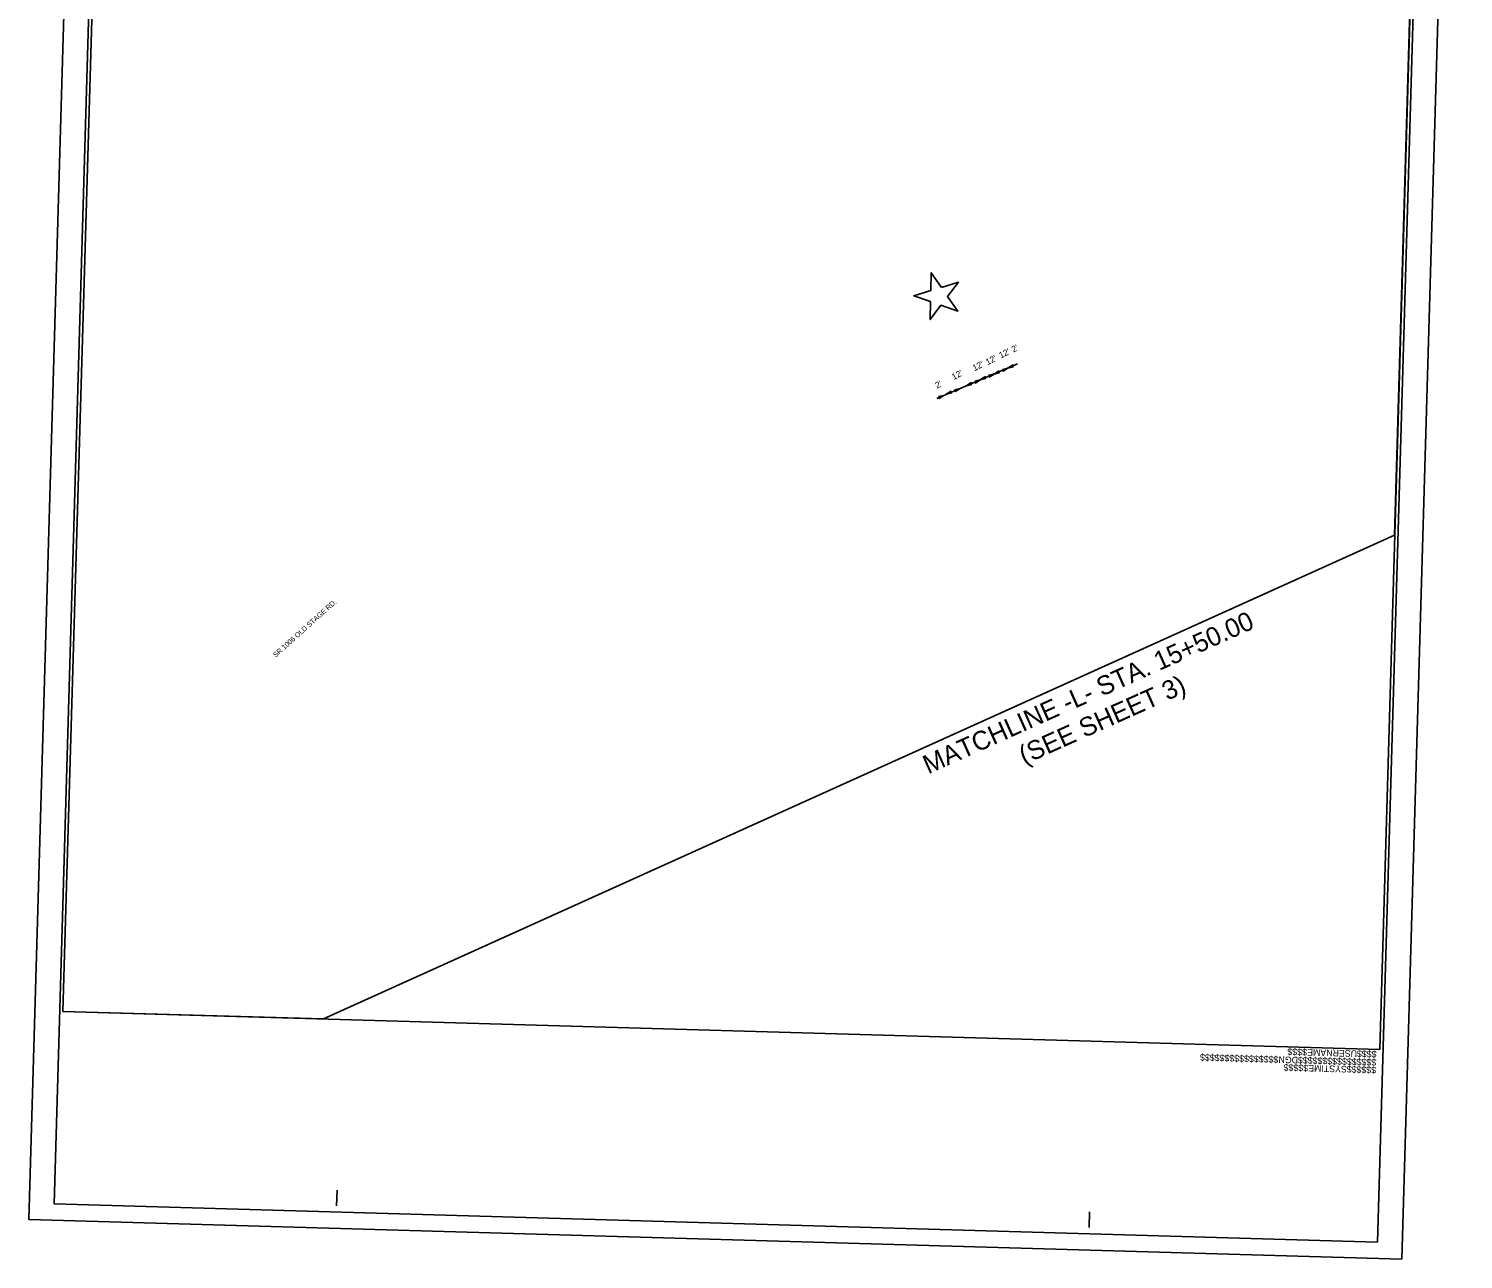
# Model space of a CAD drawing. Extents: x 2097002 to 2098146, y 685127 to 687089.
# Drawn here: x 2097002 to 2098146, y 685127 to 686108 of the extents above; entities that cross this region are included whole.
import ezdxf

# ---------------------------------------------------------------- set-up
doc = ezdxf.new("R2010")
doc.units = 0
for name, color, linetype in [('Default', 7, 'Continuous'), ('Matchline', 7, 'Continuous'), ('Matchline Text', 7, 'Continuous'), ('Sheet Layout Plan Border', 7, 'Continuous'), ('Sheet Plan CELL', 7, 'Continuous'), ('Sheet Plot Border Inside CELL', 7, 'Continuous'), ('Sheet Plot Border Outside CELL', 7, 'Continuous'), ('Text', 7, 'Continuous')]:
    doc.layers.add(name, color=color, linetype=linetype)

msp = doc.modelspace()

# ---------------------------------------------------------------- linework, layer by layer
at = {"layer": 'Default'}
msp.add_line((2097790.3, 685840.9), (2097725.9, 685813.5), dxfattribs=at)
msp.add_lwpolyline([(2097729.5, 685901.9), (2097721.4, 685913.6), (2097721.1, 685899.4), (2097707.5, 685895.2), (2097720.9, 685890.6), (2097720.7, 685876.3), (2097729.2, 685887.7), (2097742.7, 685883), (2097734.5, 685894.7), (2097743.1, 685906.1), (2097729.5, 685901.9)], dxfattribs=at)
for points in [[(2097776, 685834), (2097771.6, 685832.9), (2097775.4, 685835.4), (2097775.2, 685834.5)], [(2097778.2, 685836.6), (2097782.6, 685837.6), (2097778.8, 685835.1), (2097779, 685836.1)], [(2097787.1, 685838.7), (2097782.6, 685837.6), (2097786.5, 685840.1), (2097786.3, 685839.2)], [(2097753.9, 685824.6), (2097749.5, 685823.6), (2097753.3, 685826.1), (2097753.1, 685825.1)], [(2097756.1, 685827.2), (2097760.5, 685828.2), (2097756.7, 685825.7), (2097756.9, 685826.7)], [(2097765, 685829.3), (2097760.5, 685828.2), (2097764.4, 685830.8), (2097764.2, 685829.8)], [(2097767.1, 685831.9), (2097771.6, 685832.9), (2097767.7, 685830.4), (2097767.9, 685831.4)], [(2097727.1, 685814.9), (2097731.5, 685815.9), (2097727.7, 685813.4), (2097727.9, 685814.4)], [(2097737.9, 685817.8), (2097733.4, 685816.7), (2097737.3, 685819.2), (2097737.1, 685818.3)], [(2097740, 685820.4), (2097744.4, 685821.4), (2097740.6, 685818.9), (2097740.8, 685819.9)]]:
    msp.add_lwpolyline(points, close=True, dxfattribs=at)
at = {"layer": 'Matchline'}
msp.add_line((2097694.7, 685525.6), (2098013.7, 685669.6), dxfattribs=at)
at = {"layer": 'Sheet Layout Plan Border'}
msp.add_lwpolyline([(2098110.7, 686386.5), (2098090.8, 685704.4), (2097236.9, 685319), (2097029.4, 685325), (2097061.3, 686424.4), (2097062.8, 686473.8), (2097066.9, 686614.9), (2097306.9, 686607.9), (2097310.4, 686730.7), (2098032.5, 686709.7), (2098023.2, 686389.1)], close=True, dxfattribs=at)
at = {"layer": 'Sheet Plan CELL'}
for p, q in [((2097073, 686824.4), (2097029.4, 685325)), ((2098078.9, 685294.5), (2098122.5, 686793.8)), ((2097029.4, 685325), (2098078.9, 685294.5)), ((2098078.9, 685294.5), (2098078.9, 685294.5)), ((2097247.5, 685170.1), (2097247.8, 685182.6)), ((2097847.2, 685152.7), (2097847.6, 685165.2))]:
    msp.add_line(p, q, dxfattribs=at)
at = {"layer": 'Sheet Plot Border Inside CELL'}
msp.add_lwpolyline([(2098077, 685141), (2098125.4, 686806.2), (2097070.8, 686836.9), (2097022.4, 685171.6)], close=True, dxfattribs=at)
at = {"layer": 'Sheet Plot Border Outside CELL'}
msp.add_lwpolyline([(2098096.6, 685127.4), (2098145.5, 686810.1), (2097051, 686842), (2097002.1, 685159.2)], close=True, dxfattribs=at)

# ---------------------------------------------------------------- texts
at = {"layer": 'Matchline Text'}
for s, p in [('MATCHLINE -L- STA. 15+50.00', (2097719, 685513.8)), ('(SEE SHEET 3)', (2097795.6, 685521.4))]:
    msp.add_text(s, height=15, rotation=24.122, dxfattribs=at).set_placement(p)
at = {"layer": 'Sheet Plan CELL'}
for s, p in [('$$$$$$$$$$$$$$$$DGN$$$$$$$$$$$$$$$$', (2098076.3, 685286.9)), ('$$$$USERNAME$$$$', (2098076.5, 685293.4)), ('$$$$$$SYSTIME$$$$$', (2098076.2, 685280.8))]:
    msp.add_text(s, height=5.25, rotation=178.3348, dxfattribs=at).set_placement(p)
at = {"layer": 'Text'}
for s, height, rotation, p in [("12'", 5, 26.4485, (2097766.2, 685839.8)), ("12'", 5, 26.4485, (2097776.9, 685845.2)), ("2'", 5, 26.4485, (2097786.9, 685849.9)), ("12'", 5, 28.3682, (2097739.4, 685828)), ("12'", 5, 26.4485, (2097755.8, 685835.1)), ("2'", 5, 28.3682, (2097726.2, 685821.2)), ('SR 1006 OLD STAGE RD.', 4, 41.8984, (2097199, 685606.8))]:
    msp.add_text(s, height=height, rotation=rotation, dxfattribs=at).set_placement(p)

doc.saveas('drawing.dxf')
